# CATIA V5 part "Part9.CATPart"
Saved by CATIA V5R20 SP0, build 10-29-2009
Part number: 9FP1808M6
Revision: ANY
Definition: UNKNOWN
Nomenclature: 9FP1808M6
Source: Unknown
Bounding box of the stored display mesh (mm): x -8.9 to 8.9, y 0 to 8, z -8.9 to 8.9
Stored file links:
  C:\Users\Utente\Desktop\IO LAVORO\3D X SITO CF\CUMSA\3D files PW\pw101830\pw101830_injection\Part9.CATPart
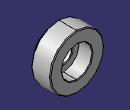
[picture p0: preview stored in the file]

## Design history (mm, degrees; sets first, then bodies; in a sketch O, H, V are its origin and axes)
Body1 "Chaflán1" (main body)
  Solid1: solid without history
